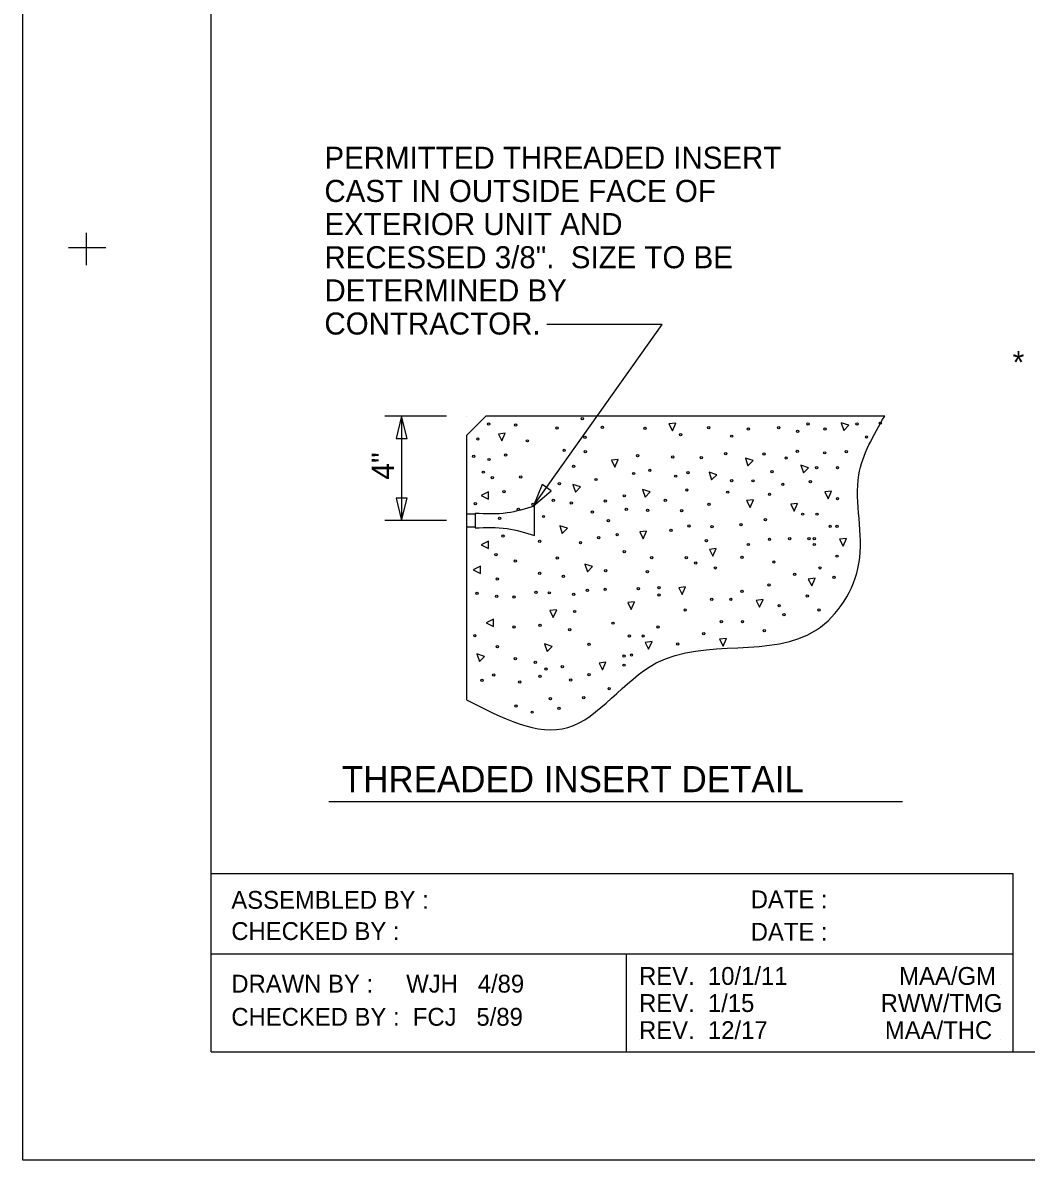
# Model space of a CAD drawing. Extents: x -408 to -23, y -15 to 117.
# Drawn here: x -367.99 to -361.59, y 12.72 to 19.97 of the extents above; entities that cross this region are included whole.
import ezdxf

# ---------------------------------------------------------------- set-up
doc = ezdxf.new("R2010")
doc.units = 0
for name, color, linetype in [('Arrowhead Terminators CELL', 7, 'Continuous'), ('Dimension Lines', 7, 'Continuous'), ('Plan Sheet', 7, 'Continuous'), ('Plot Shape', 7, 'Continuous'), ('Rebar Lines', 7, 'Continuous'), ('Rebar Lines CELL', 7, 'Continuous'), ('Sup Concrete Girder Lines', 7, 'Continuous'), ('Text', 7, 'Continuous'), ('User Information Notes', 7, 'Continuous')]:
    doc.layers.add(name, color=color, linetype=linetype)

msp = doc.modelspace()

# ---------------------------------------------------------------- linework, layer by layer
at = {"layer": 'Arrowhead Terminators CELL'}
for points in [[(-365.5776, 17.4616), (-365.6133, 17.3191), (-365.542, 17.3191)], [(-364.7352, 16.8884), (-364.6237, 16.9841), (-364.6819, 17.0253)], [(-364.7352, 16.8884), (-364.6237, 16.9841), (-364.6819, 17.0253)], [(-365.5776, 16.795), (-365.542, 16.9375), (-365.6133, 16.9375)]]:
    msp.add_lwpolyline(points, close=True, dxfattribs=at)
at = {"layer": 'Dimension Lines'}
for p, q in [((-365.2907, 17.4616), (-365.685, 17.4616)), ((-365.5776, 17.4616), (-365.5776, 16.795)), ((-365.2907, 16.795), (-365.685, 16.795))]:
    msp.add_line(p, q, dxfattribs=at)
msp.add_lwpolyline([(-364.7352, 16.8884), (-363.9153, 18.0463), (-364.6519, 18.0463)], dxfattribs=at)
at = {"layer": 'Plan Sheet'}
for p, q in [((-366.7929, 13.4063), (-366.7929, 37.3463)), ((-367.587, 18.4235), (-367.587, 18.6299)), ((-367.7036, 18.5364), (-367.4642, 18.5364)), ((-366.7929, 14.5436), (-361.6757, 14.5436)), ((-361.6757, 13.4063), (-361.6757, 14.5436)), ((-361.6757, 14.5436), (-361.6757, 14.5436)), ((-361.6757, 14.0293), (-366.7929, 14.0293)), ((-364.1439, 13.4063), (-364.1439, 14.0293)), ((-366.7929, 13.4063), (-361.6757, 13.4063)), ((-366.7929, 13.4063), (-330.3125, 13.4063)), ((-367.9945, 12.7153), (-367.9945, 12.7153))]:
    msp.add_line(p, q, dxfattribs=at)
at = {"layer": 'Plot Shape'}
msp.add_lwpolyline([(-367.9945, 37.7953), (-330.3025, 37.7953), (-330.3025, 12.7153), (-367.9945, 12.7153)], close=True, dxfattribs=at)
at = {"layer": 'Rebar Lines'}
for p, q in [((-365.109, 16.8366), (-365.1647, 16.8366)), ((-365.109, 16.7533), (-365.1647, 16.7533))]:
    msp.add_line(p, q, dxfattribs=at)
at = {"layer": 'Rebar Lines CELL'}
for p, q in [((-364.7295, 16.795), (-364.7295, 16.8898)), ((-364.7295, 16.7002), (-364.7295, 16.795))]:
    msp.add_line(p, q, dxfattribs=at)
for points in [[(-365.109, 16.8422), (-364.9044, 16.8459), (-364.7295, 16.8898)], [(-365.109, 16.7477), (-364.9044, 16.744), (-364.7295, 16.7002)]]:
    msp.add_spline(points, degree=3, dxfattribs=at)
at = {"layer": 'Sup Concrete Girder Lines'}
for points in [[(-362.4957, 17.4616), (-365.0397, 17.4616), (-365.1647, 17.3366), (-365.1647, 15.6513)], [(-363.8505, 17.3676), (-363.8287, 17.4165), (-363.8723, 17.4111), (-363.8505, 17.3676)], [(-362.7565, 17.3696), (-362.7238, 17.4024), (-362.7728, 17.4186), (-362.7565, 17.3696)], [(-364.9384, 17.3032), (-364.9166, 17.3521), (-364.9602, 17.3467), (-364.9384, 17.3032)], [(-363.3681, 17.1443), (-363.3354, 17.177), (-363.3843, 17.1933), (-363.3681, 17.1443)], [(-364.2174, 17.1359), (-364.1956, 17.1849), (-364.2391, 17.1794), (-364.2174, 17.1359)], [(-363.014, 17.0992), (-362.9813, 17.1319), (-363.0303, 17.1482), (-363.014, 17.0992)], [(-363.5999, 17.0541), (-363.5672, 17.0868), (-363.6161, 17.1031), (-363.5999, 17.0541)], [(-365.0235, 16.9316), (-365.0234, 16.9778), (-365.0695, 16.9546), (-365.0235, 16.9316)], [(-364.4689, 16.9769), (-364.4362, 17.0096), (-364.4852, 17.0259), (-364.4689, 16.9769)], [(-364.0248, 16.9448), (-363.9921, 16.9775), (-364.041, 16.9937), (-364.0248, 16.9448)], [(-362.8563, 16.9337), (-362.8346, 16.9826), (-362.8781, 16.9772), (-362.8563, 16.9337)], [(-363.3548, 16.8784), (-363.333, 16.9274), (-363.3765, 16.9219), (-363.3548, 16.8784)], [(-363.0732, 16.8557), (-363.0514, 16.9046), (-363.095, 16.8992), (-363.0732, 16.8557)], [(-364.5526, 16.713), (-364.5199, 16.7457), (-364.5688, 16.7619), (-364.5526, 16.713)], [(-364.0372, 16.6788), (-364.0154, 16.7278), (-364.0589, 16.7224), (-364.0372, 16.6788)], [(-365.0235, 16.6162), (-365.0234, 16.6625), (-365.0695, 16.6393), (-365.0235, 16.6162)], [(-363.5917, 16.5675), (-363.5699, 16.6164), (-363.6134, 16.611), (-363.5917, 16.5675)], [(-362.7615, 16.6319), (-362.7397, 16.6809), (-362.7832, 16.6754), (-362.7615, 16.6319)], [(-365.0743, 16.4569), (-365.0742, 16.5031), (-365.1203, 16.4799), (-365.0743, 16.4569)], [(-364.3916, 16.4684), (-364.3589, 16.5011), (-364.4079, 16.5174), (-364.3916, 16.4684)], [(-362.9614, 16.3776), (-362.9396, 16.4266), (-362.9832, 16.4212), (-362.9614, 16.3776)], [(-363.7882, 16.3234), (-363.7664, 16.3723), (-363.81, 16.3669), (-363.7882, 16.3234)], [(-364.1135, 16.2284), (-364.0917, 16.2774), (-364.1353, 16.272), (-364.1135, 16.2284)], [(-363.2935, 16.242), (-363.2717, 16.2909), (-363.3152, 16.2855), (-363.2935, 16.242)], [(-364.6101, 16.1767), (-364.5883, 16.2257), (-364.6318, 16.2203), (-364.6101, 16.1767)], [(-364.9923, 16.1199), (-364.9922, 16.1661), (-365.0383, 16.1429), (-364.9923, 16.1199)], [(-363.5273, 15.9945), (-363.5055, 16.0434), (-363.5491, 16.038), (-363.5273, 15.9945)], [(-364.6491, 15.9599), (-364.6164, 15.9926), (-364.6654, 16.0088), (-364.6491, 15.9599)], [(-364.0017, 15.9741), (-363.9799, 16.0231), (-364.0235, 16.0177), (-364.0017, 15.9741)], [(-365.0805, 15.8955), (-365.0478, 15.9282), (-365.0967, 15.9444), (-365.0805, 15.8955)], [(-364.2965, 15.8419), (-364.2747, 15.8909), (-364.3183, 15.8854), (-364.2965, 15.8419)]]:
    msp.add_lwpolyline(points, dxfattribs=at)
for centre in [(-365.0225, 17.4101), (-364.8504, 17.4043), (-364.4255, 17.4441), (-362.9846, 17.4108), (-362.6727, 17.4114), (-362.5238, 17.416), (-364.5856, 17.3854), (-364.2971, 17.3902), (-364.0252, 17.3831), (-363.7974, 17.3435), (-363.6185, 17.3878), (-363.4712, 17.3332), (-363.3655, 17.3783), (-363.1715, 17.3878), (-363.0519, 17.3642), (-362.876, 17.3783), (-365.0915, 17.3144), (-364.7751, 17.3034), (-364.4082, 17.3263), (-362.6118, 17.328), (-365.1175, 17.2053), (-364.9142, 17.2128), (-364.5406, 17.2435), (-364.4058, 17.234), (-364.0725, 17.2081), (-363.8478, 17.2009), (-363.6657, 17.1962), (-363.5097, 17.2223), (-363.2661, 17.2199), (-363.1243, 17.1934), (-363.0533, 17.2364), (-362.8784, 17.2269), (-362.7413, 17.2348), (-365.0206, 17.1844), (-364.4807, 17.1416), (-363.994, 17.1157), (-362.9304, 17.1324), (-362.7968, 17.1324), (-365.0565, 17.1036), (-364.9993, 17.0686), (-364.8173, 17.0733), (-364.3373, 17.0567), (-364.0976, 17.0951), (-363.8289, 17.078), (-363.7508, 17.1002), (-363.4718, 17.0496), (-363.3366, 17.0484), (-363.2141, 17.1064), (-362.9696, 17.043), (-364.9249, 16.9788), (-364.5713, 17.0307), (-363.758, 16.9905), (-363.4971, 16.976), (-363.1456, 17.026), (-365.1073, 16.9035), (-364.7392, 16.8983), (-364.6101, 16.9242), (-364.4957, 16.9078), (-364.2788, 16.919), (-364.1576, 16.9527), (-363.8957, 16.9242), (-363.6161, 16.8983), (-363.2307, 16.9621), (-362.7968, 16.9345), (-364.8327, 16.8673), (-364.3609, 16.8487), (-364.1442, 16.8673), (-364.0086, 16.8605), (-363.7911, 16.8581), (-363.0199, 16.8357), (-362.9284, 16.8357), (-364.9521, 16.8085), (-364.6723, 16.8207), (-364.2581, 16.7948), (-363.745, 16.7608), (-363.5972, 16.7564), (-363.4128, 16.7683), (-363.2567, 16.8014), (-362.8437, 16.7577), (-362.7997, 16.7577), (-364.931, 16.6964), (-364.3202, 16.6861), (-364.2025, 16.7044), (-363.8597, 16.7328), (-363.1012, 16.6797), (-362.9793, 16.6797), (-362.9454, 16.6797), (-364.6966, 16.6618), (-364.4365, 16.6548), (-363.6333, 16.6662), (-363.3656, 16.6424), (-363.2307, 16.6759), (-362.9454, 16.6424), (-364.9757, 16.5767), (-364.8528, 16.5365), (-364.5842, 16.5566), (-364.1576, 16.5957), (-363.9823, 16.5577), (-363.762, 16.5577), (-363.4062, 16.5611), (-362.7997, 16.5679), (-364.2758, 16.4751), (-364.0094, 16.4695), (-363.701, 16.5238), (-363.5757, 16.4933), (-363.2029, 16.5306), (-362.9081, 16.4933), (-364.9673, 16.422), (-364.6966, 16.4585), (-364.5454, 16.4395), (-363.0707, 16.4526), (-362.82, 16.4322), (-365.0963, 16.3308), (-364.7203, 16.3379), (-364.636, 16.334), (-364.4791, 16.3237), (-364.3927, 16.3495), (-364.2791, 16.3564), (-364.067, 16.361), (-363.9348, 16.3678), (-363.9348, 16.3203), (-363.4062, 16.3441), (-363.2334, 16.3848), (-364.971, 16.3119), (-364.8599, 16.3068), (-363.5994, 16.2932), (-363.4774, 16.2932), (-363.169, 16.2525), (-362.9894, 16.3136), (-364.4744, 16.215), (-363.7688, 16.2254), (-363.1385, 16.1949), (-362.9149, 16.2254), (-364.8599, 16.1169), (-364.6943, 16.1275), (-364.5052, 16.0991), (-364.2297, 16.1406), (-363.9416, 16.1169), (-363.5384, 16.1508), (-363.4028, 16.1508), (-365.1105, 16.0613), (-364.1246, 16.0593), (-364.0365, 16.0593), (-363.6502, 16.0728), (-363.2639, 16.0932), (-364.9662, 15.9904), (-364.3821, 16.005), (-364.3821, 16.005), (-363.8162, 16.0084), (-364.8528, 15.9146), (-364.7251, 15.891), (-364.1585, 15.9304), (-364.1111, 15.9372), (-364.9899, 15.8107), (-364.6567, 15.8475), (-364.5525, 15.8627), (-364.3821, 15.8118), (-364.1585, 15.8728), (-365.0656, 15.7752), (-364.8243, 15.7657), (-364.6943, 15.8012), (-364.4988, 15.7773), (-364.416, 15.666), (-364.2534, 15.7236), (-364.848, 15.6119), (-364.6281, 15.6592), (-364.5737, 15.5975), (-364.7447, 15.5731)]:
    msp.add_circle(centre, 0.00729, dxfattribs=at)
msp.add_spline([(-365.1647, 15.6513), (-364.5174, 15.4749), (-363.9532, 15.8866), (-362.9306, 16.0983), (-362.6602, 16.5217), (-362.6602, 17.0862), (-362.4957, 17.4616)], degree=3, dxfattribs=at)
at = {"layer": 'Text'}
for p, q in [((-365.109, 16.8422), (-365.109, 16.7477)), ((-362.3814, 15.0001), (-366.0417, 15.0001))]:
    msp.add_line(p, q, dxfattribs=at)
at = {"layer": 'User Information Notes'}
for p, q in [((-365.1647, 17.4616), (-365.1647, 17.4616)), ((-365.1647, 17.4616), (-365.1647, 17.4616)), ((-364.0627, 13.8337), (-364.0627, 13.8337)), ((-361.7569, 13.8337), (-361.7569, 13.8337)), ((-364.0627, 13.661), (-364.0627, 13.661)), ((-361.7569, 13.661), (-361.7569, 13.661)), ((-364.0627, 13.4883), (-364.0627, 13.4883)), ((-361.7569, 13.4883), (-361.7569, 13.4883))]:
    msp.add_line(p, q, dxfattribs=at)

# ---------------------------------------------------------------- texts
at = {"layer": 'Plan Sheet'}
for s, height, p in [('ASSEMBLED BY :', 0.113712, (-366.6639, 14.319)), ('DATE :', 0.11371, (-363.3504, 14.3224)), ('CHECKED BY :', 0.113712, (-366.6639, 14.12)), ('DATE :', 0.11371, (-363.3504, 14.1157)), ('REV.  10/1/11', 0.113698, (-364.0627, 13.8337)), ('MAA/GM', 0.1137, (-362.4033, 13.8337)), ('DRAWN BY :     WJH   4/89', 0.113762, (-366.6639, 13.7845)), ('REV.  1/15', 0.1137, (-364.0627, 13.661)), ('RWW/TMG', 0.1137, (-362.5215, 13.661)), ('CHECKED BY :  FCJ   5/89', 0.113762, (-366.6639, 13.5731)), ('REV.  12/17', 0.113698, (-364.0627, 13.4883)), ('MAA/THC', 0.1137, (-362.4946, 13.4883))]:
    msp.add_text(s, height=height, dxfattribs=at).set_placement(p)
at = {"layer": 'Text'}
for s, height, p in [('PERMITTED THREADED INSERT', 0.140625, (-366.07, 19.0384)), ('CAST IN OUTSIDE FACE OF', 0.140625, (-366.07, 18.8269)), ('EXTERIOR UNIT AND', 0.140625, (-366.07, 18.6155)), ('RECESSED 3/8".  SIZE TO BE', 0.140625, (-366.07, 18.4041)), ('DETERMINED BY', 0.140625, (-366.07, 18.1927)), ('CONTRACTOR.', 0.140625, (-366.07, 17.9812)), ('THREADED INSERT DETAIL', 0.166667, (-365.9589, 15.0626))]:
    msp.add_text(s, height=height, dxfattribs=at).set_placement(p)
msp.add_text('4"', height=0.143, rotation=90, dxfattribs=at).set_placement((-365.6258, 17.0558))
at = {"layer": 'User Information Notes'}
msp.add_text('*', height=0.143, dxfattribs=at).set_placement((-361.6798, 17.7331))

doc.saveas('drawing.dxf')
